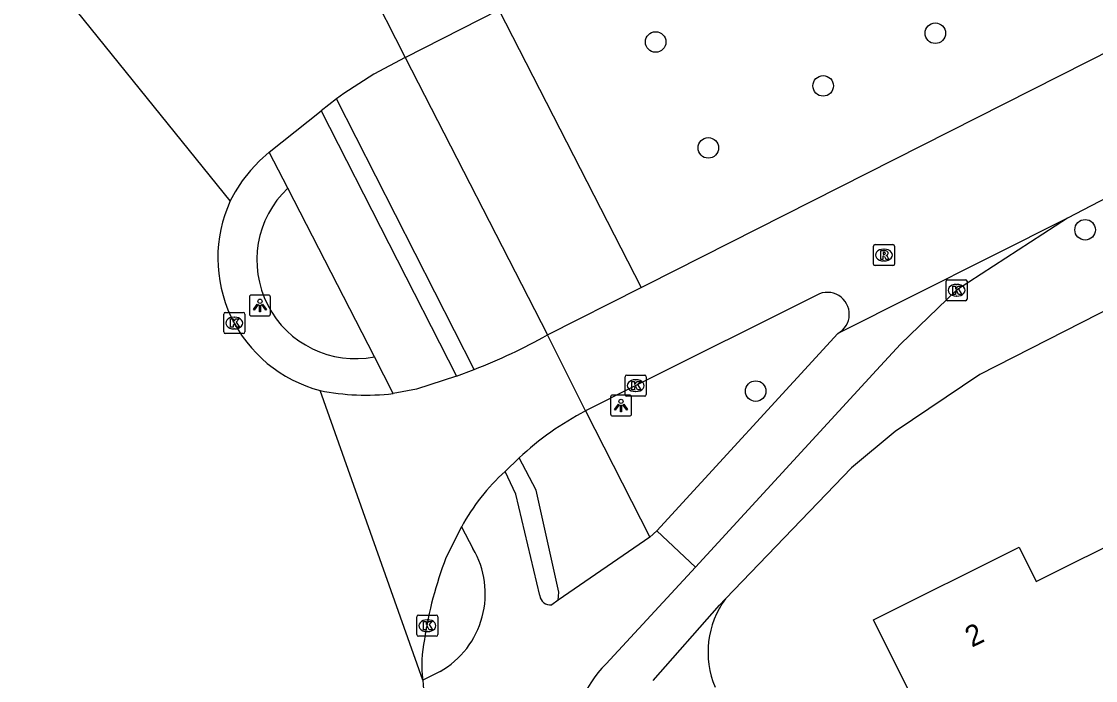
# Model space of a CAD drawing. Extents: x 162722 to 165099, y 384721 to 386283.
# Drawn here: x 163594 to 163645.1, y 384940.5 to 384971.9 of the extents above; entities that cross this region are included whole.
import ezdxf

# ---------------------------------------------------------------- set-up
doc = ezdxf.new("R2010")
doc.units = 0
for name, color, linetype in [('IMGEO_Berm_groen', 7, 'Continuous'), ('IMGEO_Boom', 7, 'Continuous'), ('IMGEO_Fietspad_gesloten', 7, 'Continuous'), ('IMGEO_Fietspad_open', 7, 'Continuous'), ('IMGEO_Kolk', 7, 'Continuous'), ('IMGEO_Lichtpunt', 7, 'Continuous'), ('IMGEO_Pand', 7, 'Continuous'), ('IMGEO_Pand_nummerreeks', 7, 'Continuous'), ('IMGEO_Rijbaan_lokaal_gesloten', 7, 'Continuous'), ('IMGEO_Rijbaan_lokaal_open', 7, 'Continuous'), ('IMGEO_Rioolput', 7, 'Continuous'), ('IMGEO_Verkeerseiland_groen', 7, 'Continuous'), ('IMGEO_Verkeerseiland_open', 7, 'Continuous'), ('IMGEO_Voetpad_open', 7, 'Continuous')]:
    doc.layers.add(name, color=color, linetype=linetype)

msp = doc.modelspace()

# ---------------------------------------------------------------- linework, layer by layer
at = {"layer": 'IMGEO_Berm_groen'}
msp.add_arc((163630.936, 384941.858), 4.303, 143.8027, 202.776, dxfattribs=at)
at = {"layer": 'IMGEO_Boom'}
for centre in [(163637.443, 384971.307), (163624.142, 384970.89), (163632.109, 384968.801), (163626.647, 384965.85), (163644.568, 384961.955), (163628.901, 384954.279)]:
    msp.add_circle(centre, 0.489, dxfattribs=at)
at = {"layer": 'IMGEO_Fietspad_gesloten'}
for points in [[(163608.237, 384967.62), (163614.676, 384954.988)], [(163606.647, 384963.933), (163605.766, 384965.649)], [(163610.765, 384955.911), (163606.647, 384963.933)], [(163611.662, 384954.164), (163610.765, 384955.911)], [(163618.629, 384944.549), (163617.497, 384949.377), (163616.983, 384950.452)], [(163614.904, 384947.813), (163615.451, 384946.793)], [(163624.199, 384947.63), (163623.863, 384947.325)], [(163626.042, 384945.9), (163624.199, 384947.63)], [(163623.863, 384947.325), (163619.504, 384944.324)], [(163621.795, 384941.309), (163626.042, 384945.9)], [(163619.504, 384944.324), (163619.199, 384944.112)], [(163613.893, 384940.933), (163613.069, 384940.525)]]:
    msp.add_lwpolyline(points, dxfattribs=at)
for centre, radius, start, end in [((163611.77, 384944.634), 4.267, 299.8317, 30.3907), ((163619.124, 384944.604), 0.498, 186.3698, 278.6778), ((163625.355, 384937.671), 5.09, 134.3777, 187.2082)]:
    msp.add_arc(centre, radius, start, end, dxfattribs=at)
at = {"layer": 'IMGEO_Fietspad_open'}
for points in [[(163643.731, 384962.5), (163638.454, 384959.078), (163635.78, 384956.505), (163634.652, 384955.269), (163626.042, 384945.9)], [(163624.199, 384947.63), (163632.803, 384957.024)]]:
    msp.add_lwpolyline(points, dxfattribs=at)
at = {"layer": 'IMGEO_Kolk'}
for p, q in [((163637.953, 384958.652), (163637.953, 384959.504)), ((163638.028, 384959.578), (163638.88, 384959.578)), ((163638.441, 384959.358), (163638.466, 384959.358)), ((163638.954, 384959.504), (163638.954, 384958.652)), ((163638.464, 384958.798), (163638.439, 384958.798)), ((163638.88, 384958.578), (163638.028, 384958.578)), ((163603.601, 384957.091), (163603.601, 384957.943)), ((163603.676, 384958.017), (163604.528, 384958.017)), ((163604.089, 384957.797), (163604.114, 384957.797)), ((163604.602, 384957.943), (163604.602, 384957.091)), ((163604.112, 384957.237), (163604.087, 384957.237)), ((163604.528, 384957.017), (163603.676, 384957.017)), ((163622.693, 384954.113), (163622.693, 384954.965)), ((163622.768, 384955.039), (163623.62, 384955.039)), ((163623.181, 384954.819), (163623.206, 384954.819)), ((163623.694, 384954.965), (163623.694, 384954.113)), ((163623.204, 384954.259), (163623.179, 384954.259)), ((163623.62, 384954.039), (163622.768, 384954.039)), ((163612.783, 384942.691), (163612.783, 384943.543)), ((163612.858, 384943.617), (163613.71, 384943.617)), ((163613.271, 384943.397), (163613.296, 384943.397)), ((163613.784, 384943.543), (163613.784, 384942.691)), ((163613.71, 384942.617), (163612.858, 384942.617)), ((163613.294, 384942.837), (163613.269, 384942.837))]:
    msp.add_line(p, q, dxfattribs=at)
for points in [[(163637.953, 384958.652), (163637.953, 384959.504)], [(163638.028, 384959.578), (163638.88, 384959.578)], [(163638.274, 384959.278), (163638.397, 384959.278), (163638.397, 384959.127), (163638.527, 384959.278), (163638.691, 384959.278), (163638.545, 384959.127), (163638.698, 384958.878), (163638.546, 384958.878), (163638.461, 384959.042), (163638.397, 384958.975), (163638.397, 384958.878), (163638.274, 384958.878), (163638.274, 384959.278)], [(163638.954, 384959.504), (163638.954, 384958.652)], [(163638.88, 384958.578), (163638.028, 384958.578)], [(163603.601, 384957.091), (163603.601, 384957.943)], [(163603.676, 384958.017), (163604.528, 384958.017)], [(163603.922, 384957.717), (163604.045, 384957.717), (163604.045, 384957.566), (163604.175, 384957.717), (163604.339, 384957.717), (163604.193, 384957.566), (163604.346, 384957.317), (163604.194, 384957.317), (163604.109, 384957.481), (163604.045, 384957.414), (163604.045, 384957.317), (163603.922, 384957.317), (163603.922, 384957.717)], [(163604.602, 384957.943), (163604.602, 384957.091)], [(163604.528, 384957.017), (163603.676, 384957.017)], [(163622.693, 384954.113), (163622.693, 384954.965)], [(163622.768, 384955.039), (163623.62, 384955.039)], [(163623.014, 384954.739), (163623.137, 384954.739), (163623.137, 384954.588), (163623.267, 384954.739), (163623.431, 384954.739), (163623.285, 384954.588), (163623.438, 384954.339), (163623.286, 384954.339), (163623.201, 384954.503), (163623.137, 384954.436), (163623.137, 384954.339), (163623.014, 384954.339), (163623.014, 384954.739)], [(163623.694, 384954.965), (163623.694, 384954.113)], [(163623.62, 384954.039), (163622.768, 384954.039)], [(163612.783, 384942.691), (163612.783, 384943.543)], [(163612.858, 384943.617), (163613.71, 384943.617)], [(163613.784, 384943.543), (163613.784, 384942.691)], [(163613.104, 384943.317), (163613.227, 384943.317), (163613.227, 384943.166), (163613.357, 384943.317), (163613.521, 384943.317), (163613.375, 384943.166), (163613.528, 384942.917), (163613.376, 384942.917), (163613.291, 384943.081), (163613.227, 384943.014), (163613.227, 384942.917), (163613.104, 384942.917), (163613.104, 384943.317)], [(163613.71, 384942.617), (163612.858, 384942.617)]]:
    msp.add_lwpolyline(points, dxfattribs=at)
for centre, start, end in [((163638.03, 384959.502), 91.552, 178.448), ((163638.03, 384959.502), 91.552, 178.448), ((163638.878, 384959.502), 1.552, 88.448), ((163638.878, 384959.502), 1.552, 88.448), ((163638.03, 384958.654), 181.552, 268.448), ((163638.03, 384958.654), 181.552, 268.448), ((163638.878, 384958.654), 271.552, 358.448), ((163638.878, 384958.654), 271.552, 358.448), ((163603.678, 384957.941), 91.552, 178.448), ((163603.678, 384957.941), 91.552, 178.448), ((163604.526, 384957.941), 1.552, 88.448), ((163604.526, 384957.941), 1.552, 88.448), ((163603.678, 384957.093), 181.552, 268.448), ((163603.678, 384957.093), 181.552, 268.448), ((163604.526, 384957.093), 271.552, 358.448), ((163604.526, 384957.093), 271.552, 358.448), ((163622.77, 384954.963), 91.552, 178.448), ((163622.77, 384954.963), 91.552, 178.448), ((163623.618, 384954.963), 1.552, 88.448), ((163623.618, 384954.963), 1.552, 88.448), ((163622.77, 384954.115), 181.552, 268.448), ((163622.77, 384954.115), 181.552, 268.448), ((163623.618, 384954.115), 271.552, 358.448), ((163623.618, 384954.115), 271.552, 358.448), ((163612.86, 384943.541), 91.552, 178.448), ((163612.86, 384943.541), 91.552, 178.448), ((163613.708, 384943.541), 1.552, 88.448), ((163613.708, 384943.541), 1.552, 88.448), ((163612.86, 384942.693), 181.552, 268.448), ((163612.86, 384942.693), 181.552, 268.448), ((163613.708, 384942.693), 271.552, 358.448), ((163613.708, 384942.693), 271.552, 358.448)]:
    msp.add_arc(centre, 0.0765, start, end, dxfattribs=at)
for centre, major_axis, ratio, start_param, end_param in [((163638.44, 384959.078), (-0.387, 0.002), 0.722429, 4.712389, 7.853982), ((163638.465, 384959.078), (-0.39, 0.002), 0.717154, 1.570796, 4.712389), ((163604.088, 384957.517), (-0.387, 0.002), 0.722429, 4.712389, 7.853982), ((163604.113, 384957.517), (-0.39, 0.002), 0.717154, 1.570796, 4.712389), ((163623.18, 384954.539), (-0.387, 0.002), 0.722429, 4.712389, 7.853982), ((163623.205, 384954.539), (-0.39, 0.002), 0.717154, 1.570796, 4.712389), ((163613.27, 384943.117), (-0.387, 0.002), 0.722429, 4.712389, 7.853982), ((163613.295, 384943.117), (-0.39, 0.002), 0.717154, 1.570796, 4.712389)]:
    msp.add_ellipse(centre, major_axis=major_axis, ratio=ratio, start_param=start_param, end_param=end_param, dxfattribs=at)
at = {"layer": 'IMGEO_Lichtpunt'}
for p, q in [((163604.823, 384958.756), (163604.823, 384957.949)), ((163604.823, 384958.756), (163604.823, 384957.949)), ((163605.725, 384958.851), (163604.917, 384958.851)), ((163605.725, 384958.851), (163604.917, 384958.851)), ((163605.819, 384957.949), (163605.819, 384958.756)), ((163605.819, 384957.949), (163605.819, 384958.756)), ((163604.917, 384957.855), (163605.725, 384957.855)), ((163604.917, 384957.855), (163605.725, 384957.855)), ((163622.9, 384954.092), (163622.092, 384954.092)), ((163622.9, 384954.092), (163622.092, 384954.092)), ((163621.998, 384953.997), (163621.998, 384953.19)), ((163621.998, 384953.997), (163621.998, 384953.19)), ((163622.994, 384953.19), (163622.994, 384953.997)), ((163622.994, 384953.19), (163622.994, 384953.997)), ((163622.092, 384953.096), (163622.9, 384953.096)), ((163622.092, 384953.096), (163622.9, 384953.096))]:
    msp.add_line(p, q, dxfattribs=at)
for points in [[(163605.197, 384958.42), (163605.236, 384958.392), (163605.048, 384958.13), (163605.01, 384958.157), (163605.197, 384958.42)], [(163605.299, 384958.372), (163605.346, 384958.372), (163605.346, 384958.05), (163605.299, 384958.05), (163605.299, 384958.372)], [(163605.409, 384958.392), (163605.447, 384958.419), (163605.634, 384958.157), (163605.595, 384958.129), (163605.409, 384958.392)], [(163622.372, 384953.661), (163622.411, 384953.633), (163622.223, 384953.371), (163622.185, 384953.398), (163622.372, 384953.661)], [(163622.474, 384953.613), (163622.521, 384953.613), (163622.521, 384953.291), (163622.474, 384953.291), (163622.474, 384953.613)], [(163622.584, 384953.633), (163622.622, 384953.66), (163622.809, 384953.398), (163622.77, 384953.37), (163622.584, 384953.633)]]:
    msp.add_lwpolyline(points, dxfattribs=at)
for centre in [(163605.322, 384958.554), (163622.497, 384953.795)]:
    msp.add_circle(centre, 0.0994, dxfattribs=at)
for centre, start, end in [((163604.917, 384958.756), 90, 180), ((163604.917, 384958.756), 90, 180), ((163605.725, 384958.756), 0, 90), ((163605.725, 384958.756), 0, 90), ((163604.917, 384957.949), 180, 270), ((163604.917, 384957.949), 180, 270), ((163605.725, 384957.949), 270, 0), ((163605.725, 384957.949), 270, 360), ((163622.092, 384953.997), 90, 180), ((163622.092, 384953.997), 90, 180), ((163622.9, 384953.997), 0, 90), ((163622.9, 384953.997), 0, 90), ((163622.092, 384953.19), 180, 270), ((163622.092, 384953.19), 180, 270), ((163622.9, 384953.19), 270, 0), ((163622.9, 384953.19), 270, 360)]:
    msp.add_arc(centre, 0.0946, start, end, dxfattribs=at)
at = {"layer": 'IMGEO_Pand'}
msp.add_lwpolyline([(163649.213, 384930.337), (163648.201, 384932.371), (163643.97, 384930.266), (163642.165, 384933.895), (163639.816, 384932.727), (163634.505, 384943.403), (163641.429, 384946.847), (163642.236, 384945.225), (163646.981, 384947.585), (163651.375, 384938.752), (163652.6, 384939.361), (163655.527, 384933.478), (163649.213, 384930.337)], dxfattribs=at)
at = {"layer": 'IMGEO_Rijbaan_lokaal_gesloten'}
for points in [[(163603.913, 384963.327), (163593.981, 384975.642)], [(163610.401, 384973.756), (163612.225, 384970.148)], [(163612.225, 384970.148), (163610.732, 384969.361), (163609.316, 384968.444), (163608.959, 384968.183)], [(163608.959, 384968.183), (163608.237, 384967.62)], [(163605.766, 384965.649), (163608.237, 384967.62)], [(163605.766, 384965.649), (163605.298, 384965.231), (163604.869, 384964.774), (163604.483, 384964.279), (163604.142, 384963.752), (163603.913, 384963.327)], [(163620.8, 384953.334), (163618.991, 384956.952)], [(163614.676, 384954.988), (163615.509, 384955.308)], [(163614.676, 384954.988), (163612.774, 384954.367), (163611.662, 384954.164)], [(163613.069, 384940.525), (163608.18, 384954.309)], [(163617.651, 384951.107), (163616.983, 384950.452)], [(163614.904, 384947.813), (163614.17, 384946.348)]]:
    msp.add_lwpolyline(points, dxfattribs=at)
for centre, radius, start, end in [((163609.833, 384960.61), 6.514, 155.3473, 255.2964), ((163605.925, 384980.117), 26.596, 291.1227, 299.4253), ((163610.367, 384964.953), 10.866, 258.3874, 276.8435), ((163627.741, 384940.179), 14.873, 117.8185, 132.7181), ((163623.63, 384943.077), 9.928, 132.0279, 151.5101), ((163631.633, 384939.653), 18.703, 159.0233, 171.3546), ((163619.014, 384941.269), 5.991, 168.4953, 187.1335), ((163641.453, 384942.055), 28.425, 183.0852, 190.0736)]:
    msp.add_arc(centre, radius, start, end, dxfattribs=at)
at = {"layer": 'IMGEO_Rijbaan_lokaal_open'}
for points in [[(163623.451, 384959.212), (163623.737, 384959.356), (163672.137, 384983.875)], [(163612.225, 384970.148), (163616.682, 384972.414)], [(163648.716, 384965.114), (163648.623, 384965.068), (163643.731, 384962.5)], [(163643.731, 384962.5), (163632.803, 384957.024)], [(163618.991, 384956.952), (163623.451, 384959.212)], [(163631.813, 384958.848), (163623.194, 384954.539), (163620.8, 384953.334)]]:
    msp.add_lwpolyline(points, dxfattribs=at)
msp.add_arc((163632.314, 384957.939), 1.038, 298.1225, 118.8605, dxfattribs=at)
at = {"layer": 'IMGEO_Rioolput'}
for p, q in [((163634.575, 384961.252), (163635.427, 384961.252)), ((163634.5, 384960.326), (163634.5, 384961.178)), ((163634.988, 384961.032), (163635.013, 384961.032)), ((163635.501, 384961.178), (163635.501, 384960.326)), ((163635.427, 384960.252), (163634.575, 384960.252)), ((163635.011, 384960.472), (163634.986, 384960.472))]:
    msp.add_line(p, q, dxfattribs=at)
for points in [[(163634.575, 384961.252), (163635.427, 384961.252)], [(163634.5, 384960.326), (163634.5, 384961.178)], [(163635.089, 384960.95), (163634.837, 384960.952), (163634.837, 384960.552)], [(163635.015, 384960.871), (163634.961, 384960.871), (163634.961, 384960.79)], [(163634.961, 384960.79), (163635.013, 384960.79)], [(163635.501, 384961.178), (163635.501, 384960.326)], [(163635.427, 384960.252), (163634.575, 384960.252)], [(163634.837, 384960.552), (163634.961, 384960.552), (163634.961, 384960.714), (163634.972, 384960.714)], [(163635.019, 384960.685), (163635.09, 384960.552), (163635.23, 384960.552), (163635.165, 384960.678)]]:
    msp.add_lwpolyline(points, dxfattribs=at)
for centre, radius, start, end in [((163634.577, 384961.176), 0.0765, 91.552, 178.448), ((163634.577, 384961.176), 0.0765, 91.552, 178.448), ((163635.425, 384961.176), 0.0765, 1.552, 88.448), ((163635.425, 384961.176), 0.0765, 1.552, 88.448), ((163634.997, 384960.979), 0.19, 274.7715, 282.9687), ((163635.021, 384960.775), 0.0964, 77.0061, 93.1865), ((163635.035, 384960.832), 0.0378, 276.6634, 79.6772), ((163635.088, 384960.84), 0.109, 350.3612, 89.416), ((163635.086, 384960.84), 0.112, 277.5842, 350.9817), ((163635.07, 384960.625), 0.108, 29.5134, 73.7905), ((163634.577, 384960.328), 0.0765, 181.552, 268.448), ((163634.577, 384960.328), 0.0765, 181.552, 268.448), ((163634.971, 384960.661), 0.0533, 26.0293, 88.6989), ((163635.425, 384960.328), 0.0765, 271.552, 358.448), ((163635.425, 384960.328), 0.0765, 271.552, 358.448)]:
    msp.add_arc(centre, radius, start, end, dxfattribs=at)
for centre, major_axis, ratio, start_param, end_param in [((163634.987, 384960.752), (-0.387, 0.002), 0.722429, 4.712389, 7.853982), ((163635.012, 384960.752), (-0.39, 0.002), 0.717154, 1.570796, 4.712389)]:
    msp.add_ellipse(centre, major_axis=major_axis, ratio=ratio, start_param=start_param, end_param=end_param, dxfattribs=at)
at = {"layer": 'IMGEO_Verkeerseiland_groen'}
msp.add_lwpolyline([(163616.682, 384972.414), (163623.451, 384959.212)], dxfattribs=at)
at = {"layer": 'IMGEO_Verkeerseiland_open'}
msp.add_arc((163609.868, 384960.519), 4.694, 133.3298, 281.0165, dxfattribs=at)
at = {"layer": 'IMGEO_Voetpad_open'}
for points in [[(163683.732, 384974.099), (163682.29, 384976.876), (163639.563, 384955.061), (163635.539, 384952.364), (163633.451, 384950.624), (163627.464, 384944.399)], [(163612.225, 384970.148), (163618.991, 384956.952)], [(163615.509, 384955.308), (163608.959, 384968.183)], [(163620.8, 384953.334), (163623.863, 384947.325)], [(163619.504, 384944.324), (163619.538, 384944.719), (163618.456, 384949.572), (163617.651, 384951.107)], [(163624.016, 384940.508), (163627.176, 384944.099), (163627.464, 384944.399)]]:
    msp.add_lwpolyline(points, dxfattribs=at)

# ---------------------------------------------------------------- texts
at = {"layer": 'IMGEO_Pand_nummerreeks'}
msp.add_text('2', height=1, rotation=26.4458, dxfattribs=at).set_placement((163639.179, 384942.064))

doc.saveas('drawing.dxf')
